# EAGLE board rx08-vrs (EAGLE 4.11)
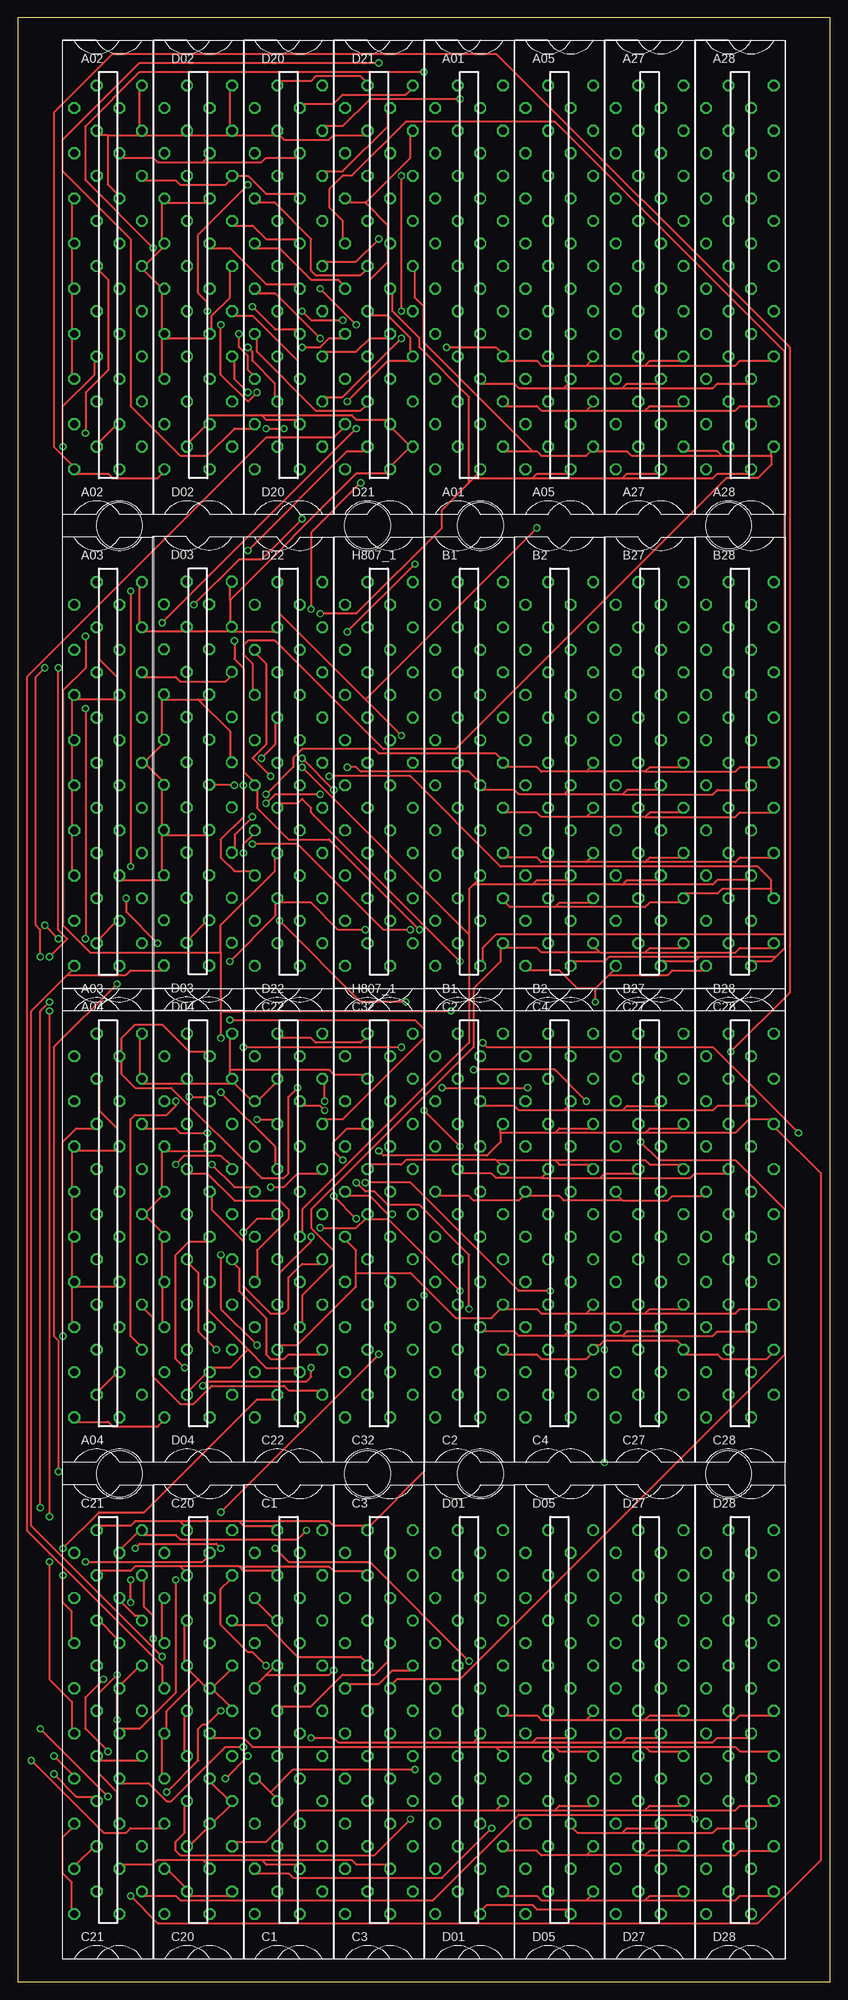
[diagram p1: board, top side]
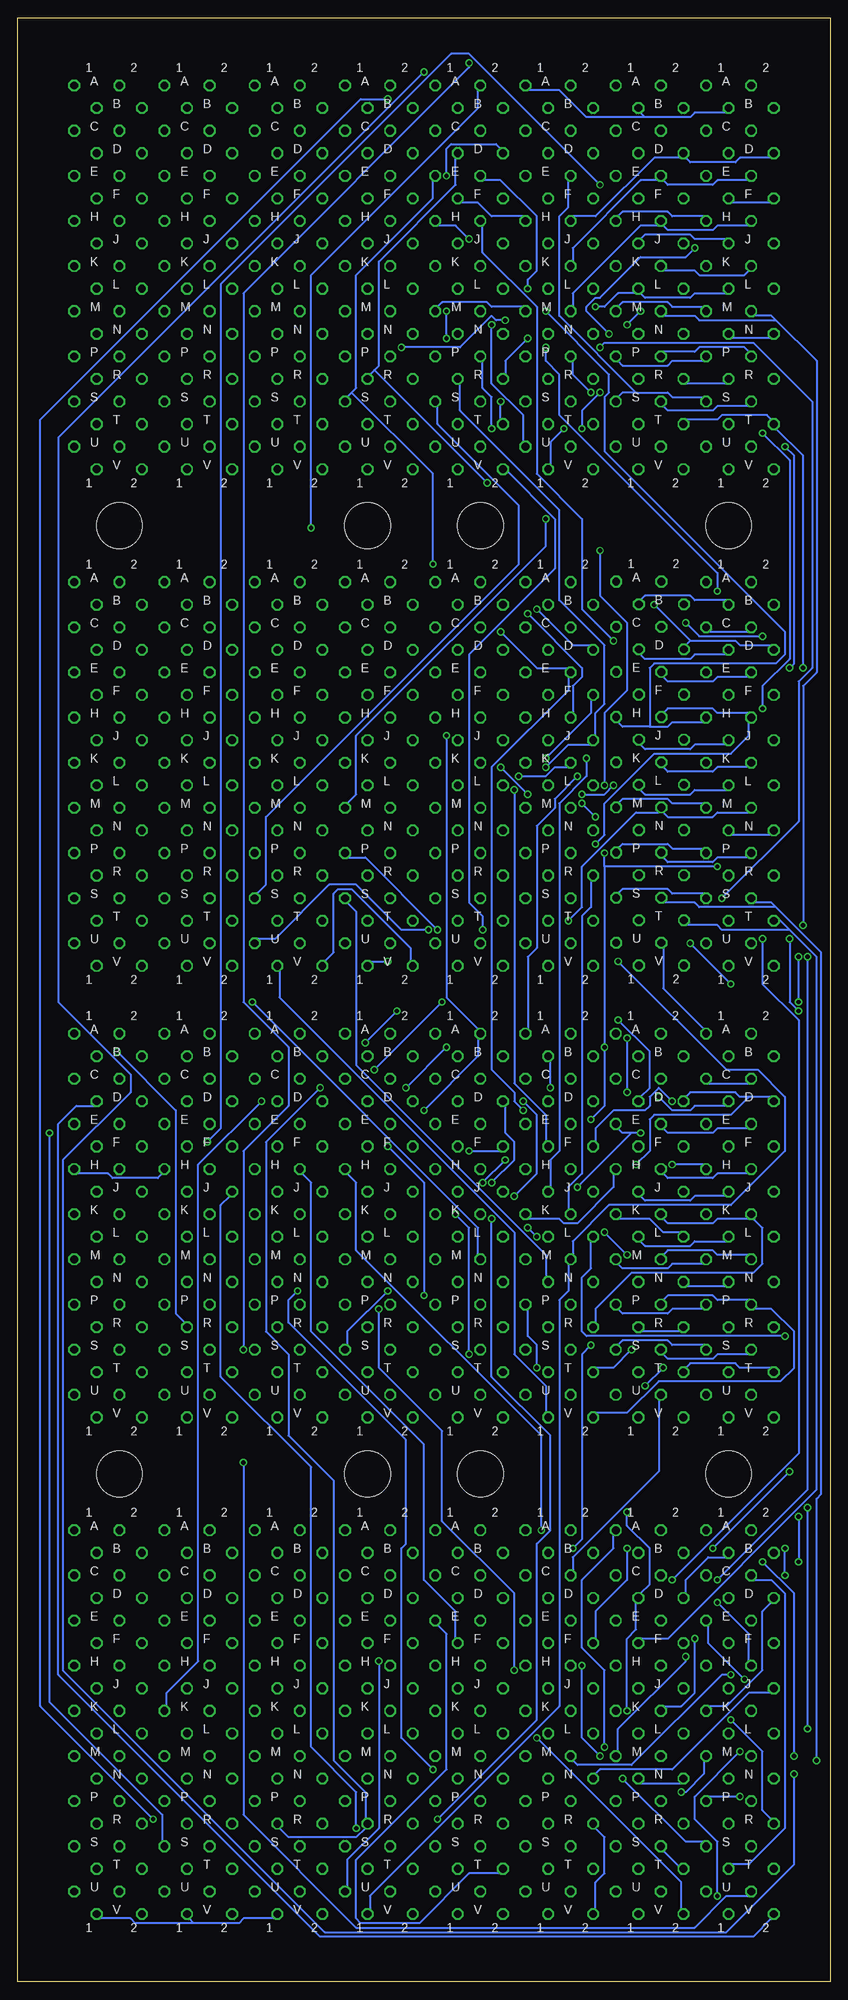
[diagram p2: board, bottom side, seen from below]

Size 114.3 x 276.23 mm. Coordinates in mm from the lower left corner, seen from the top.
Outline: 0,0 114.3,0 114.3,276.23 0,276.23 0,0
Copper layers (1*16): Top 0.035mm / dielectric 1.5mm / Bottom 0.035mm
Design rules "olimex10mil": minimum track width 10mil, minimum drill 24mil, track to track 10mil, track to pad 10mil, pad to pad 10mil, via to via 10mil, smd to smd 10mil, copper to edge 40mil, drill to drill 10mil, minimum pad ring 10mil, minimum via ring 8mil, stop-mask expansion 0mil, vias tented up to drill 0mil, thermal gap 10mil
Net classes: 1 Supply: width 1.905 mm, drill 0.508 mm

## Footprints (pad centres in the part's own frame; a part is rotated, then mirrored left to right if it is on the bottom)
H807 = drill 1.092 octagon: A1 4.763,28.575; A2 -1.587,28.575; B1 1.587,25.4; B2 -4.763,25.4; C1 4.763,22.225; C2 -1.587,22.225; D1 1.587,19.05; D2 -4.763,19.05; E1 4.763,15.875; E2 -1.587,15.875; F1 1.587,12.7; F2 -4.763,12.7; H1 4.763,9.525; H2 -1.587,9.525; J1 1.587,6.35; J2 -4.763,6.35; K1 4.763,3.175; K2 -1.587,3.175; L1 1.587,0; L2 -4.763,0; M1 4.763,-3.175; M2 -1.587,-3.175; N1 1.587,-6.35; N2 -4.763,-6.35; P1 4.763,-9.525; P2 -1.587,-9.525; R1 1.587,-12.7; R2 -4.763,-12.7; S1 4.763,-15.875; S2 -1.587,-15.875; T1 1.587,-19.05; T2 -4.763,-19.05; U1 4.763,-22.225; U2 -1.587,-22.225; V1 1.587,-25.4; V2 -4.763,-25.4
CBLOCK = hole 6.452: 7.938,68.263; 42.862,68.263

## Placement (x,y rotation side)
A01  [H807]  63.5,238.12 0 top
A02  M903  [H807]  12.7,238.12 0 top
A03  M903  [H807]  12.7,168.28 0 top
A04  M903  [H807]  12.7,104.78 0 top
A05  [H807]  76.2,238.12 0 top
A27  [H807]  88.9,238.12 0 top
A28  [H807]  101.6,238.12 0 top
B1  [H807]  63.5,168.28 0 top
B2  [H807]  76.2,168.28 0 top
B27  [H807]  88.9,168.28 0 top
B28  [H807]  101.6,168.28 0 top
C1  [H807]  38.1,34.92 0 top
C2  [H807]  63.5,104.78 0 top
C3  M310  [H807]  50.8,34.92 0 top
C4  [H807]  76.2,104.78 0 top
C20  [H807]  25.4,34.92 0 top
C21  [H807]  12.7,34.92 0 top
C22  M624  [H807]  38.1,104.78 0 top
C27  [H807]  88.9,104.78 0 top
C28  [H807]  101.6,104.78 0 top
C32  M002  [H807]  50.8,104.78 0 top
D01  [H807]  63.5,34.92 0 top
D02  M903  [H807]  25.4,238.12 0 top
D03  M903  [H807]  25.34,168.34 0 top
D04  M903  [H807]  25.4,104.78 0 top
D05  [H807]  76.2,34.92 0 top
D20  [H807]  38.1,238.12 0 top
D21  [H807]  50.8,238.12 0 top
D22  M002  [H807]  38.1,168.28 0 top
D27  [H807]  88.9,34.92 0 top
D28  [H807]  101.6,34.92 0 top
H807_1  H807  [H807]  50.8,168.28 0 top
U$1  [CBLOCK]  6.35,136.53 0 top
U$2  [CBLOCK]  57.15,136.53 0 top
U$3  [CBLOCK]  6.35,3.17 0 top
U$4  [CBLOCK]  57.15,3.17 0 top

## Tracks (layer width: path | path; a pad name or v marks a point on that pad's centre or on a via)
AC00L  (via drill 0.61)
  Top 0.254: D04.B1 26.67,130.81 24.13,130.81 20.32,134.62 16.51,134.62 14.61,132.72 14.61,130.81 A04.B1 14.61,129.54 14.61,127.64 16.51,125.73 21.59,125.73 34.29,113.03 37.47,113.03 38.1,113.67 38.1,124.46 v39.37,125.73
  Bottom 0.254: v39.37,125.73 39.37,129.54 C22.B1
AC01L  (via drill 0.61)
  Top 0.254: v24.13,124.46 26.67,124.46 D04.D1 | v29.84,135.25 55.88,135.25 57.15,133.99 57.15,132.72 45.72,121.28 43.18,121.28 C22.E1
  Bottom 0.254: v24.13,124.46 22.23,122.56 19.68,122.56 19.05,123.19 14.61,123.19 A04.D1 | v29.84,135.25 25.4,130.81 25.4,125.73 26.67,124.46 D04.D1
AC02L  (via drill 0.61)
  Top 0.254: v26.67,119.38 22.86,119.38 22.23,120.02 17.78,120.02 A04.E1 | v35.56,111.76 37.47,111.76 39.37,113.67 42.55,113.67 C22.H1
  Bottom 0.254: 27.94,119.38 29.21,119.38 29.84,120.02 D04.E1 | v26.67,119.38 27.94,119.38 | 27.94,119.38 v35.56,111.76
AC03L  (via drill 0.61)
  Top 0.254: v22.23,114.94 23.5,116.2 28.57,116.2 29.84,114.94 D04.H1
  Bottom 0.254: v22.23,114.94 17.78,114.94 A04.H1 | C22.K1 42.55,107.31 38.1,107.31 37.47,106.68 35.56,106.68 30.48,111.76 30.48,113.67 D04.H1
AC04L
  Top 0.254: C22.M1 42.55,100.97 40.01,100.97 38.1,99.06 38.1,94.61 37.47,93.98 35.56,93.98 31.75,97.79 31.75,104.14 27.3,108.58 27.3,110.49 D04.J1
  Bottom 0.254: A04.J1 14.61,110.49 19.05,110.49 19.68,109.86 26.04,109.86 26.67,110.49 D04.J1
AC05L  (via drill 0.61)
  Top 0.254: v41.27,86.36 41.27,85.09 40.64,84.45 26.67,84.45 v26.04,83.82 | v23.5,86.36 22.23,87.63 22.23,102.23 24.13,104.14 26.67,104.14 D04.L1
  Bottom 0.254: A04.L1 14.61,104.14 19.05,104.14 19.68,103.5 26.04,103.5 26.67,104.14 D04.L1 | v41.27,86.36 41.27,89.53 42.55,90.81 42.55,94.61 C22.P1 | v23.5,86.36 v26.04,83.82
AC06L
  Top 0.254: C22.S1 42.55,88.27 38.1,88.27 37.47,87.63 35.56,87.63 34.92,88.27 34.92,93.34 31.11,97.16 31.11,100.33 30.48,100.97 D04.M1
  Bottom 0.254: A04.M1 17.78,100.97 22.23,100.97 22.86,100.33 29.21,100.33 29.84,100.97 D04.M1
AC07L
  Top 0.254: C22.U1 42.55,83.19 38.1,83.19 37.47,83.82 27.3,83.82 24.77,81.28 22.86,81.28 19.05,85.09 19.05,93.34 17.78,94.61 A04.P1
  Bottom 0.254: A04.P1 17.78,94.61 22.23,94.61 22.86,93.98 29.21,93.98 29.84,94.61 D04.P1
AC08L  (via drill 0.61)
  Top 0.254: v22.23,123.83 22.23,123.19 20.95,121.92 16.51,121.92 15.88,121.28 15.88,90.81 17.14,89.53 A04.S1
  Bottom 0.254: A04.S1 17.78,89.53 22.23,89.53 22.86,90.17 29.21,90.17 29.84,89.53 D04.S1 | v22.23,123.83 24.13,125.73 25.4,124.46 25.4,123.19 26.04,122.56 30.48,122.56 33.02,120.02 33.02,118.11 C22.F2
AC09L  (via drill 0.61)
  Top 0.254: v27.3,114.94 30.48,111.76 33.02,111.76 C22.J2
  Bottom 0.254: 11.43,124.46 12.7,124.46 13.34,125.09 19.68,125.09 20.32,124.46 D04.D2 | 11.43,124.46 8.26,124.46 A04.D2 | v27.3,114.94 25.4,116.84 25.4,121.28 24.77,121.92 13.97,121.92 11.43,124.46
AC10L  (via drill 0.61)
  Top 0.254: v6.35,90.81 6.35,118.11 8.26,120.02 10.79,120.02 A04.E2
  Bottom 0.254: A04.E2 11.43,120.02 15.88,120.02 16.51,119.38 22.86,119.38 23.5,120.02 D04.E2 | v6.35,90.81 34.29,90.81 34.92,91.44 34.92,99.06 33.66,100.33 33.66,104.14 C22.L2
AC11L
  Top 0.254: C22.N2 33.66,99.06 33.66,102.87 38.1,107.31 38.1,108.58 36.83,109.86 30.48,109.86 26.67,113.67 24.13,113.67 D04.H2
  Bottom 0.254: A04.H2 11.43,113.67 15.88,113.67 16.51,113.03 22.86,113.03 23.5,113.67 D04.H2
BAC00
  Bottom 0.254: 26.04,262.25 19.68,262.25 19.05,262.89 14.61,262.89 A02.B1 | 26.04,262.25 26.67,262.89 D02.B1 | 26.04,262.25 34.29,262.25 38.1,266.06 42.55,266.06 D20.A1
BAC01
  Top 0.254: 26.04,255.91 19.68,255.91 19.05,256.54 14.61,256.54 A02.D1 | 26.04,255.91 26.67,256.54 D02.D1 | 26.04,255.91 34.29,255.91 34.92,256.54 39.37,256.54 D20.D1
BAC02
  Top 0.254: A02.E1 17.78,253.37 22.23,253.37 22.86,252.73 29.21,252.73 29.84,253.37 D02.E1 32.38,254 34.92,251.46 39.37,251.46 D20.F1
BAC03
  Top 0.254: D20.J1 39.37,245.11 34.92,245.11 33.02,247.01 30.48,247.01 D02.H1
  Bottom 0.254: A02.H1 17.78,248.28 22.23,248.28 22.86,248.92 29.21,248.92 29.84,248.28 D02.H1
BAC04
  Top 0.254: D20.L1 39.37,238.76 34.92,238.76 29.84,243.84 27.3,243.84 D02.J1
  Bottom 0.254: A02.J1 14.61,245.11 19.05,245.11 19.68,245.75 26.04,245.75 26.67,245.11 D02.J1
BAC05  (via drill 0.61)
  Top 0.254: v33.02,235.59 36.2,232.41 39.37,232.41 D20.N1
  Bottom 0.254: A02.L1 14.61,237.49 19.05,237.49 19.68,236.85 26.04,236.85 26.67,237.49 D02.L1 27.3,237.49 29.84,237.49 31.75,235.59 v33.02,235.59
BAC06
  Top 0.254: D20.R1 39.37,226.06 39.37,227.97 33.02,234.31 30.48,234.31 D02.M1
  Bottom 0.254: A02.M1 17.78,235.59 22.23,235.59 22.86,236.22 29.21,236.22 29.84,235.59 D02.M1
BAC07  (via drill 0.61)
  Top 0.254: v34.92,218.44 v37.47,218.44 | v32.38,223.52 30.48,225.43 30.48,227.97 D02.P1
  Bottom 0.254: A02.P1 17.78,227.97 22.23,227.97 22.86,227.33 29.21,227.33 29.84,227.97 D02.P1 | v37.47,218.44 39.37,216.53 39.37,213.36 D20.V1 | v34.92,218.44 34.92,220.98 v32.38,223.52
BAC08
  Bottom 0.254: 27.3,223.52 29.21,223.52 29.84,222.88 D02.S1 | 27.3,223.52 22.86,223.52 22.23,222.88 17.78,222.88 A02.S1 | 27.3,223.52 38.1,234.31 38.1,248.28 36.83,249.56 36.83,253.37 D20.E2
BAC09
  Bottom 0.254: A02.D2 8.26,256.54 12.7,256.54 13.34,255.91 19.68,255.91 20.32,256.54 D02.D2 20.95,256.54 24.77,256.54 33.02,248.28 36.2,248.28 D20.H2
BAC10
  Bottom 0.254: A02.E2 11.43,253.37 15.88,253.37 16.51,252.73 22.86,252.73 23.5,253.37 D02.E2 24.13,253.37 26.67,253.37 36.2,243.84 36.2,241.94 D20.K2
BAC11
  Bottom 0.254: A02.H2 11.43,247.01 15.88,247.01 16.51,246.38 22.86,246.38 23.5,247.01 D02.H2 24.13,247.01 26.67,247.01 36.2,237.49 36.2,235.59 D20.M2
BACLR
  Bottom 0.254: D04.P2 23.5,95.89 22.86,96.52 16.51,96.52 15.88,95.89 11.43,95.89 A04.P2 10.79,94.61 8.26,94.61 5.08,91.44 5.08,86.36 6.99,84.45 24.13,84.45 28.57,80.01 33.02,80.01 C22.V2
BINIT  (via drill 0.61)
  Top 0.254: D02.V2 20.32,212.09 19.68,211.46 13.34,211.46 12.7,212.09 8.26,212.09 A02.V2 7.62,213.36 5.08,215.9 5.08,262.89 13.34,271.14 67.31,271.14 108.58,229.87 108.58,139.06 v100.33,130.81 | 76.83,90.81 70.48,90.81 69.85,91.44 65.41,91.44 C2.R1 | 76.83,90.81 77.47,91.44 C4.R1 | 85.09,90.81 85.72,91.44 90.17,91.44 C27.R1 | 85.09,90.81 76.83,90.81 | 85.09,90.81 97.79,90.81 98.42,91.44 102.87,91.44 C28.R1
  Bottom 0.254: v100.33,130.81 92.08,122.56 92.08,93.98 90.81,92.71 C27.R1
BIOP1  (via drill 0.61)
  Top 0.254: v22.23,56.52 22.23,40.64 17.14,35.56 14.61,35.56 C21.L1 | v9.53,179.07 v9.53,146.69 | v9.53,217.81 9.53,223.52 12.7,226.69 12.7,239.4 11.43,240.66 A02.K2
  Bottom 0.254: v22.23,56.52 4.45,74.3 4.45,135.25 9.53,140.34 v9.53,146.69 | v9.53,179.07 9.53,182.25 5.71,186.06 5.71,214 v9.53,217.81 | D02.K2 23.5,240.66 19.05,240.66 18.41,240.03 12.06,240.03 11.43,240.66 A02.K2
BIOP2  (via drill 0.61)
  Top 0.254: v4.45,59.05 4.45,42.55 7.62,39.37 7.62,35.56 C21.L2 | v4.45,136.53 v4.45,65.41 | v3.81,148.59 v5.71,146.69
  Bottom 0.254: v4.45,65.41 v4.45,59.05 | v4.45,136.53 5.71,137.79 v5.71,146.69 | v3.81,148.59 3.81,182.25 1.91,184.15 1.91,227.97 7.62,233.68 | 7.62,233.68 8.26,234.31 10.79,234.31 A02.M2 | 7.62,233.68 18.41,233.68 19.05,234.31 23.5,234.31 D02.M2
BIOP4  (via drill 0.61)
  Top 0.254: v3.17,35.56 v12.7,26.04 | v3.17,66.67 3.17,136.53 v4.45,137.79 | v4.45,144.15 6.99,146.69 5.71,147.96 v5.71,184.78 | v6.35,215.9 6.35,221.62 10.79,226.06 10.79,227.97 A02.P2
  Bottom 0.254: v12.7,26.04 17.14,26.04 C21.P1 | v3.17,35.56 v3.17,66.67 | v4.45,137.79 v4.45,144.15 | v5.71,184.78 5.08,185.42 5.08,214.63 v6.35,215.9 | D02.P2 23.5,229.24 19.05,229.24 18.41,229.87 12.06,229.87 11.43,229.24 A02.P2
BIRQ  (via drill 0.61)
  Top 0.254: v27.94,88.9 25.4,91.44 25.4,99.69 24.13,100.97 D04.M2
  Bottom 0.254: A04.M2 11.43,102.23 15.88,102.23 16.51,102.87 22.86,102.87 23.5,102.23 D04.M2 | v27.94,88.9 30.48,86.36 33.02,86.36 C22.T2
BMB00
  Bottom 0.254: A03.B1 14.61,194.31 19.05,194.31 19.68,194.94 26.04,194.94 26.67,194.31 D03.B1
BMB01
  Bottom 0.254: A03.D1 14.61,186.69 19.05,186.69 19.68,186.06 26.04,186.06 26.67,186.69 D03.D1
BMB02
  Top 0.254: A03.E1 17.78,183.51 22.23,183.51 22.86,182.88 29.21,182.88 29.84,183.51 D03.E1
BMB03
  Bottom 0.254: A03.J1 14.61,173.99 19.05,173.99 19.68,173.35 26.04,173.35 26.67,173.99 D03.J1
BMB03L  (via drill 0.61)
  Top 0.254: 80.01,227.33 73.66,227.33 73.03,227.97 68.58,227.97 A01.P1 67.94,229.24 67.31,229.87 v60.33,229.87 | 80.01,227.33 80.64,227.97 A05.P1 | 88.27,227.33 88.9,227.97 93.34,227.97 A27.P1 | 80.01,227.33 88.27,227.33 | 88.27,227.33 100.97,227.33 101.6,227.97 106.05,227.97 A28.P1 | v40.01,234.95 41.27,233.68 v45.72,233.68
  Bottom 0.254: 25.4,176.53 29.21,176.53 29.84,177.16 D03.H1 | 25.4,176.53 22.86,176.53 22.23,177.16 17.78,177.16 A03.H1 | 25.4,176.53 25.4,184.78 24.77,185.42 7.62,185.42 6.35,186.69 6.35,189.87 31.75,215.26 31.75,222.88 31.11,223.52 31.11,226.06 v40.01,234.95 | v45.72,233.68 46.99,233.68 47.62,234.31 52.07,229.87 v60.33,229.87
BMB04
  Bottom 0.254: A03.M1 17.78,165.74 22.23,165.74 22.86,166.37 29.21,166.37 29.84,165.74 D03.M1
BMB04L  (via drill 0.61)
  Top 0.254: 80.01,170.18 73.66,170.18 73.03,170.81 68.58,170.81 B1.K1 67.94,172.09 67.31,172.72 50.8,172.72 50.16,173.35 40.01,173.35 38.73,172.09 38.73,170.81 v34.92,167 | 80.01,170.18 80.64,170.81 B2.K1 | 88.27,170.18 88.9,170.81 93.34,170.81 B27.K1 | 88.27,170.18 80.01,170.18 | 88.27,170.18 100.97,170.18 101.6,170.81 106.05,170.81 B28.K1 | v30.48,168.28 27.3,168.28 D03.L1
  Bottom 0.254: A03.L1 14.61,167.64 19.05,167.64 19.68,167 26.04,167 26.67,167.64 D03.L1 | v30.48,168.28 31.75,167 v34.92,167
BMB05
  Bottom 0.254: A03.S1 17.78,153.03 22.23,153.03 22.86,153.67 29.21,153.67 29.84,153.03 D03.S1
BMB05L  (via drill 0.61)
  Top 0.254: 76.83,167 70.48,167 69.85,167.64 65.41,167.64 B1.L1 64.77,168.91 63.5,170.18 48.26,170.18 47.62,170.81 v46.35,170.81 | 76.83,167 77.47,167.64 B2.L1 | 85.09,167 85.72,167.64 90.17,167.64 B27.L1 | 85.09,167 76.83,167 | 85.09,167 97.79,167 98.42,167.64 102.87,167.64 B28.L1 | v33.02,163.83 30.48,161.29 30.48,159.38 D03.P1 | v34.92,165.74 36.2,167 v42.55,167
  Bottom 0.254: A03.P1 17.78,159.38 22.23,159.38 22.86,160.02 29.21,160.02 29.84,159.38 D03.P1 | v34.92,165.74 v33.02,163.83 | v46.35,170.81 v42.55,167
BMB06
  Bottom 0.254: A03.E2 11.43,183.51 15.88,183.51 16.51,182.88 22.86,182.88 23.5,183.51 D03.E2
BMB06L  (via drill 0.61)
  Top 0.254: 80.01,163.83 73.66,163.83 73.03,164.47 68.58,164.47 B1.M1 | 80.01,163.83 80.64,164.47 B2.M1 | 88.27,163.83 88.9,164.47 93.34,164.47 B27.M1 | 88.27,163.83 80.01,163.83 | 88.27,163.83 100.97,163.83 101.6,164.47 106.05,164.47 B28.M1 | v24.77,193.68 31.11,200.03 34.29,200.03 v40.01,205.74
  Bottom 0.254: 19.68,188.59 13.34,188.59 12.7,187.96 8.26,187.96 A03.D2 | 19.68,188.59 20.32,187.96 D03.D2 | v24.77,193.68 19.68,188.59 | v40.01,205.74 40.01,201.93 66.67,175.26 66.67,167 67.94,165.74 B1.M1
BMB07
  Bottom 0.254: A03.K2 11.43,170.81 15.88,170.81 16.51,170.18 22.86,170.18 23.5,170.81 D03.K2
BMB07L  (via drill 0.61)
  Top 0.254: 80.01,157.48 73.66,157.48 73.03,158.12 68.58,158.12 B1.P1 | 80.01,157.48 80.64,158.12 B2.P1 | 88.27,157.48 88.9,158.12 93.34,158.12 B27.P1 | 88.27,157.48 80.01,157.48 | 88.27,157.48 100.97,157.48 101.6,158.12 106.05,158.12 B28.P1 | v33.02,160.02 39.37,160.02 51.44,147.96 v55.24,147.96
  Bottom 0.254: D03.H2 23.5,178.44 22.86,179.07 16.51,179.07 15.88,178.44 11.43,178.44 A03.H2 11.43,177.16 11.43,175.26 13.97,172.72 24.77,172.72 31.75,165.74 31.75,161.29 v33.02,160.02 | v55.24,147.96 65.41,158.12 67.94,158.12 B1.P1
BMB08
  Bottom 0.254: A03.P2 11.43,158.12 15.88,158.12 16.51,157.48 22.86,157.48 23.5,158.12 D03.P2
BMB08L  (via drill 0.61)
  Top 0.254: 80.01,36.83 73.66,36.83 73.03,37.47 68.58,37.47 D01.K1 | 80.01,36.83 80.64,37.47 D05.K1 | 88.27,36.83 88.9,37.47 93.34,37.47 D27.K1 | 80.01,36.83 88.27,36.83 | 88.27,36.83 100.97,36.83 101.6,37.47 106.05,37.47 D28.K1 | v36.83,149.22 48.26,137.79 v54.61,137.79 | v64.14,128.27 75.56,128.27 v80.01,123.83
  Bottom 0.254: A03.M2 11.43,164.47 15.88,164.47 16.51,163.83 22.86,163.83 23.5,164.47 D03.M2 24.13,164.47 27.3,164.47 34.92,156.84 34.92,151.13 v36.83,149.22 | v64.14,128.27 v54.61,137.79 | v80.01,123.83 88.9,114.94 88.9,45.09 93.34,40.64 93.34,38.73 D27.K1
BMB09  (via drill 0.61)
  Top 0.254: v1.91,31.11 12.06,20.95 15.24,20.95 15.88,21.59 20.32,21.59 C20.R2
  Bottom 0.254: v1.91,31.11 1.91,67.94 1.27,68.58 1.27,144.78 7.62,151.13 | 7.62,151.13 8.26,151.76 10.79,151.76 A03.S2 | 7.62,151.13 18.41,151.13 19.05,151.76 23.5,151.76 D03.S2
BMB10
  Bottom 0.254: 5.71,147.96 7.62,149.86 A03.T2 | 5.71,147.96 1.91,144.15 1.91,69.22 22.86,48.26 26.67,48.26 C20.F1 | 5.71,147.96 15.24,147.96 15.88,148.59 20.32,148.59 D03.T2
BMB11  (via drill 0.61)
  Top 0.254: v20.32,45.72 1.91,64.14 1.91,136.53 6.99,141.6 | 6.99,141.6 7.62,142.24 A03.V2 | 6.99,141.6 15.24,141.6 15.88,142.24 20.32,142.24 D03.V2
  Bottom 0.254: v20.32,45.72 20.32,45.09 29.84,35.56 29.84,32.38 C20.M1
BRD_L  (via drill 0.61)
  Top 0.254: v55.24,22.86 50.16,17.78 22.86,17.78 22.23,18.41 22.23,19.68 23.5,20.95 23.5,24.77 C20.P2 | v47.62,107.31 v44.45,110.49 | v43.18,123.83 43.18,126.36 C22.C1
  Bottom 0.254: v55.24,22.86 41.27,36.83 41.27,61.59 39.37,63.5 39.37,76.83 47.62,85.09 v47.62,107.31 | v44.45,110.49 41.27,113.67 41.27,121.92 v43.18,123.83
BRUN
  Bottom 0.254: A04.S2 11.43,88.27 15.88,88.27 16.51,87.63 22.86,87.63 23.5,88.27 D04.S2
BSKIP
  Bottom 0.254: D04.K2 23.5,107.31 22.86,106.68 16.51,106.68 15.88,107.31 11.43,107.31 A04.K2 10.79,107.31 9.53,106.05 9.53,100.97 10.79,99.69 27.94,99.69 33.02,94.61 33.02,92.71 C22.R2
BTS1  (via drill 0.61)
  Top 0.254: v15.88,53.34 v15.88,56.52 | v3.17,144.15 3.17,147.96 2.54,148.59 2.54,183.51 v3.81,184.78
  Bottom 0.254: v15.88,53.34 11.43,48.9 11.43,45.09 C21.H2 | v15.88,56.52 3.17,69.22 v3.17,144.15 | v3.81,184.78 3.81,214.63 7.62,218.44 A02.T2 8.26,219.71 8.89,220.34 15.24,220.34 15.88,219.71 20.32,219.71 D02.T2
BTS3
  Bottom 0.254: A02.S2 11.43,221.62 15.88,221.62 16.51,220.98 22.86,220.98 23.5,221.62 D02.S2
BWR_L  (via drill 0.61)
  Top 0.254: 48.9,250.19 46.35,250.19 D21.F2 | 48.9,250.19 52.07,247.01 52.07,245.11 D21.J1 52.07,243.84 52.07,241.94 49.53,239.4 49.53,235.59 D21.M2 49.53,234.31 52.07,234.31 55.24,231.14 55.24,229.24 D21.P1 55.24,227.97 52.07,227.97 v46.35,222.25 | 48.9,250.19 55.24,256.54 55.24,259.71 D21.C1 | C20.J2 20.32,41.91 20.32,44.45 1.27,63.5 1.27,183.51 34.92,217.17 44.45,217.17 45.72,218.44 D21.T2
  Bottom 0.254: v46.35,222.25 46.35,219.71 D21.T2
C0L  (via drill 0.61)
  Top 0.254: C21.E1 17.14,51.44 16.51,51.44 14.61,53.34 C21.D1 | v50.8,116.84 51.44,116.2 66.04,116.2 67.94,118.11 67.94,119.38 | 67.94,119.38 67.94,120.02 C2.E1 | 75.56,119.38 76.2,120.02 80.64,120.02 C4.E1 | 75.56,119.38 67.94,119.38 | 88.27,119.38 88.9,120.02 93.34,120.02 C27.E1 | 88.27,119.38 75.56,119.38 | 88.27,119.38 100.97,119.38 102.87,121.28 106.05,121.28 C28.E1 106.68,120.02 113.03,113.67 113.03,17.14 104.14,8.26 19.68,8.26 v15.88,12.06 | v12.06,42.55 9.53,40.01 9.53,35.56 v12.7,32.38
  Bottom 0.254: v50.8,116.84 46.35,116.84 C32.F2 | v12.06,42.55 17.14,47.62 17.14,50.16 C21.E1 | v12.7,32.38 19.05,26.04 19.05,22.86 15.88,19.68 v15.88,12.06
C1L  (via drill 0.61)
  Top 0.254: C20.F2 20.32,48.26 20.32,53.34 C20.D2 | C21.B1 14.61,60.96 17.14,63.5 C21.A1 17.78,62.87 22.23,62.87 22.86,62.23 39.37,62.23 v40.64,63.5 | 67.31,115.57 54.61,115.57 53.98,114.94 49.53,114.94 C32.H2 | 67.31,115.57 67.94,114.94 C2.H1 | 75.56,115.57 76.2,114.94 80.64,114.94 C4.H1 | 67.31,115.57 75.56,115.57 | 75.56,115.57 88.27,115.57 88.9,114.94 93.34,114.94 C27.H1
  Bottom 0.254: C20.D2 20.32,54.61 20.32,56.52 17.14,59.69 14.61,59.69 C21.B1 | C28.H1 106.05,113.67 101.6,113.67 100.97,113.03 94.61,113.03 93.98,113.67 C27.H1 | v40.64,63.5 40.64,76.83 66.67,102.87 66.67,112.39 67.94,113.67 C2.H1
C20U1
  Top 0.254: 27.3,41.27 29.84,38.73 C20.K1 | 25.4,42.55 26.67,41.27 C20.J1 27.3,41.27 | 25.4,42.55 24.13,43.81 C20.H2 23.5,45.09 23.5,50.16 C20.E2 | 27.3,41.27 29.84,43.81 C20.H1 | C20.N2 20.32,29.21 20.32,34.29 C20.L2 20.95,35.56 20.95,38.1 25.4,42.55 | C20.T2 20.95,15.88 23.5,13.34 C20.U2 24.13,12.06 29.84,12.06 C20.U1 | C20.S2 24.13,19.05 26.67,21.59 C20.R1 27.3,22.23 29.84,24.77 C20.P1 29.84,25.4 27.3,27.94 C20.N1
  Bottom 0.254: C20.S2 23.5,18.41 20.95,15.88 C20.T2 | C20.N2 20.95,27.94 26.67,27.94 C20.N1
C21U1  (via drill 0.61)
  Top 0.254: v95.25,22.86 94.61,23.5 70.48,23.5 58.42,11.43 22.86,11.43 22.23,12.06 17.78,12.06 C21.U1 | v62.23,264.8 49.53,264.8 45.72,260.99 43.18,260.99 D20.C1
  Bottom 0.254: v95.25,22.86 111.12,38.73 111.12,219.71 66.04,264.8 v62.23,264.8
DATA00LL  (via drill 0.61)
  Top 0.254: v35.56,169.54 33.02,172.09 34.92,173.99 34.92,185.42 33.66,186.69 D22.D2 | 76.83,224.16 70.48,224.16 69.85,224.79 65.41,224.79 A01.R1 | 76.83,224.16 77.47,224.79 A05.R1 | 85.09,224.16 85.72,224.79 90.17,224.79 A27.R1 | 76.83,224.16 85.09,224.16 | 85.09,224.16 97.79,224.16 98.42,224.79 102.87,224.79 A28.R1 | v41.27,193.04 41.27,203.84 v48.26,210.82
  Bottom 0.254: v35.56,169.54 38.73,166.37 38.73,165.1 41.27,162.56 41.27,145.41 42.55,144.15 42.55,133.99 C22.A1 | 64.14,226.69 64.77,226.06 A01.R1 | 64.14,226.69 63.5,227.33 63.5,241.94 52.7,252.73 52.7,256.54 D21.D1 | v41.27,193.04 36.2,187.96 33.66,187.96 D22.D2 | v48.26,210.82 64.14,226.69
DATA01L  (via drill 0.61)
  Top 0.254: v43.18,122.56 42.55,123.19 40.01,123.19 C22.D1 | 80.01,220.98 73.66,220.98 73.03,221.62 68.58,221.62 A01.S1 | 80.01,220.98 80.64,221.62 A05.S1 | 88.27,220.98 88.9,221.62 93.34,221.62 A27.S1 | 80.01,220.98 88.27,220.98 | 88.27,220.98 100.97,220.98 101.6,221.62 106.05,221.62 A28.S1 | v55.88,199.39 v46.35,189.87
  Bottom 0.254: v43.18,122.56 44.45,123.83 44.45,125.09 47.62,128.27 47.62,170.81 36.83,181.61 36.83,183.51 D22.E2 36.83,184.78 41.27,184.78 v46.35,189.87 | 67.31,223.52 67.94,222.88 A01.S1 | 67.31,223.52 66.67,224.16 66.67,240.03 55.88,250.82 55.88,253.37 D21.E1 | v55.88,199.39 55.88,212.09 67.31,223.52
DATA02L  (via drill 0.61)
  Top 0.254: 72.39,215.26 73.03,215.26 73.66,214.63 80.01,214.63 80.64,215.26 A05.U1 81.28,215.26 85.72,215.26 86.36,214.63 99.06,214.63 | 72.39,215.26 68.58,215.26 A01.U1 | 72.39,215.26 57.15,230.5 57.15,235.59 55.88,236.85 55.88,240.66 D21.K1 | 106.05,214.63 106.05,215.26 A28.U1 | 106.05,214.63 106.05,213.36 104.14,211.46 99.69,211.46 61.59,173.35 51.44,173.35 36.2,188.59 32.38,188.59 31.75,187.96 31.75,186.69 33.02,185.42 33.02,181.61 D22.F2 | v40.01,172.09 v44.45,167.64 | 99.06,214.63 98.42,215.26 93.98,215.26 A27.U1 | 99.06,214.63 106.05,214.63
  Bottom 0.254: v44.45,167.64 44.45,126.36 40.01,121.92 40.01,118.11 C22.F1 | v40.01,172.09 33.66,178.44 33.66,180.34 D22.F2
DATA03L  (via drill 0.61)
  Top 0.254: v42.55,192.41 47.62,192.41 59.69,204.47 59.69,207.01 63.5,210.82 | 64.14,211.46 64.77,212.09 A01.V1 | 63.5,210.82 64.14,211.46 | v34.29,172.09 36.2,173.99 36.2,177.16 D22.H2 | 63.5,210.82 63.5,222.88 56.52,229.87 56.52,231.14 52.7,234.95 52.7,237.49 D21.L1 | 72.39,211.46 73.03,212.09 77.47,212.09 A05.V1 | 64.14,211.46 72.39,211.46 | 85.09,211.46 85.72,212.09 90.17,212.09 A27.V1 | 72.39,211.46 85.09,211.46 | 85.09,211.46 97.79,211.46 98.42,212.09 102.87,212.09 A28.V1
  Bottom 0.254: v42.55,192.41 34.92,184.78 34.92,183.51 36.2,182.25 36.2,178.44 D22.H2 | v34.29,172.09 34.29,169.54 38.1,165.74 38.1,116.84 39.37,115.57 39.37,111.76 C22.J1
DATA04L  (via drill 0.61)
  Top 0.254: 63.5,147.32 63.5,153.67 64.14,154.31 | 63.5,147.32 63.5,132.08 40.01,108.58 40.01,105.41 C22.L1 | 64.14,154.31 64.77,154.94 B1.R1 | 72.39,154.31 73.03,154.94 77.47,154.94 B2.R1 | 72.39,154.31 64.14,154.31 | 85.09,154.31 85.72,154.94 90.17,154.94 B27.R1 | 85.09,154.31 72.39,154.31 | 85.09,154.31 97.79,154.31 98.42,154.94 102.87,154.94 B28.R1 | 63.5,147.32 v40.01,170.81
  Bottom 0.254: v40.01,170.81 36.83,173.99 33.66,173.99 D22.J2 33.02,175.26 33.02,178.44 31.75,179.71 31.75,187.96 38.1,194.31 38.1,207.01 52.07,220.98 52.07,224.79 D21.R1
DATA05L  (via drill 0.61)
  Top 0.254: v43.81,169.54 55.24,169.54 67.94,156.84 104.14,156.84 106.05,154.94 106.05,153.67 | 106.05,153.67 106.05,153.03 B28.S1 | 106.05,153.67 99.06,153.67 98.42,153.03 93.98,153.03 B27.S1 93.34,151.76 88.9,151.76 88.27,151.13 75.56,151.13 | 75.56,151.13 76.2,151.76 80.64,151.76 B2.S1 | 75.56,151.13 69.22,151.13 68.58,151.76 B1.S1
  Bottom 0.254: v43.81,169.54 40.01,169.54 38.73,170.81 36.83,170.81 D22.K2 | C22.N1 40.01,99.06 40.01,102.23 66.67,128.91 66.67,150.5 67.94,151.76 B1.S1 | D21.S1 55.24,221.62 55.24,219.07 43.81,207.65 43.81,199.39 79.38,163.83 79.38,154.31 80.64,153.03 B2.S1
DATA06L  (via drill 0.61)
  Top 0.254: C22.R1 40.01,92.71 40.01,96.52 44.45,100.97 44.45,102.87 41.27,106.05 41.27,108.58 64.14,131.44 64.14,139.7 67.94,143.51 67.94,145.41 B1.U1 68.58,145.41 73.03,145.41 73.66,144.78 81.92,144.78 | v56.52,147.96 43.81,160.66 38.1,160.66 33.66,165.1 33.66,167.64 D22.L2 33.02,168.91 31.75,170.18 31.75,184.78 30.48,186.06 v30.48,188.59 | 88.27,144.78 88.9,145.41 93.34,145.41 B27.U1 | 81.92,144.78 88.27,144.78 | 81.92,144.78 81.28,145.41 B2.U1 | 88.27,144.78 100.97,144.78 101.6,145.41 106.05,145.41 B28.U1
  Bottom 0.254: v56.52,147.96 60.33,147.96 66.67,154.31 70.48,154.31 78.11,146.69 80.64,146.69 B2.U1 | v30.48,188.59 34.92,193.04 34.92,205.74 41.27,212.09 41.27,235.59 48.9,243.21 48.9,247.01 D21.H2
DATA07L  (via drill 0.61)
  Top 0.254: v62.23,143.51 41.27,164.47 41.27,165.1 40.01,166.37 39.37,165.74 36.83,165.74 D22.M2 | 107.95,147.32 107.95,145.41 106.68,144.15 | 107.95,147.32 107.95,229.24 75.56,261.62 54.61,261.62 46.99,254 45.72,254 43.81,252.09 43.81,249.56 45.72,247.65 45.72,245.11 D21.J2 | 106.68,144.15 106.05,143.51 103.5,143.51 B28.V1 | 95.89,144.15 95.25,143.51 90.81,143.51 B27.V1 | 106.68,144.15 95.89,144.15 | 107.95,147.32 67.31,147.32 65.41,145.41 65.41,143.51 B1.V1 | 95.89,144.15 83.19,144.15 82.55,143.51 78.11,143.51 B2.V1
  Bottom 0.254: C22.V1 40.01,80.01 40.01,83.82 44.45,88.27 44.45,105.41 77.47,138.43 77.47,142.24 B2.V1 | v62.23,143.51 64.77,143.51 B1.V1
DATA08L  (via drill 0.61)
  Top 0.254: 85.09,20.95 85.72,21.59 90.17,21.59 D27.R1 | 85.09,20.95 78.74,20.95 78.11,21.59 D05.R1 | 85.09,20.95 97.79,20.95 98.42,21.59 102.87,21.59 D28.R1 | v33.66,121.28 36.2,121.28 C22.E2 | v31.75,158.75 31.75,160.02 33.02,161.29 D22.N2 | v40.01,229.87 42.55,229.87 43.81,231.14 45.72,231.14 D21.N2 | v15.88,195.58 v15.88,156.84 | v59.69,125.73 v71.75,125.73 | v31.75,131.44 v53.98,131.44
  Bottom 0.254: D05.R1 77.47,21.59 76.2,20.32 66.67,20.32 65.41,21.59 D01.R1 65.41,22.86 65.41,26.67 69.85,31.11 69.85,70.48 76.2,76.83 76.2,88.27 79.38,91.44 79.38,118.11 v71.75,125.73 | v33.66,121.28 31.75,123.19 v31.75,131.44 31.75,156.84 | 31.75,156.84 v31.75,158.75 | v40.01,229.87 40.01,227.97 38.1,226.06 38.1,220.34 15.88,198.12 v15.88,195.58 | v15.88,156.84 31.75,156.84 | v53.98,131.44 v59.69,125.73
DATA09L  (via drill 0.61)
  Top 0.254: 80.01,17.78 73.66,17.78 73.03,18.41 68.58,18.41 D01.S1 | 80.01,17.78 80.64,18.41 D05.S1 | 88.27,17.78 88.9,18.41 93.34,18.41 D27.S1 | 88.27,17.78 80.01,17.78 | 88.27,17.78 100.97,17.78 101.6,18.41 106.05,18.41 D28.S1 | v28.57,125.09 36.2,117.47 36.2,114.94 C22.H2 | 28.57,144.78 28.57,148.59 36.2,156.21 36.2,158.12 D22.P2 | 28.57,144.78 28.57,136.53 | 28.57,136.53 v28.57,132.72 | v47.62,218.44 v20.32,191.13 | v9.53,189.23 9.53,184.78 6.35,181.61 6.35,148.59 10.16,144.78 28.57,144.78 | v109.86,119.38 97.79,131.44 66.04,131.44 v65.41,132.08 | 28.57,136.53 v60.96,136.53
  Bottom 0.254: v28.57,132.72 v28.57,125.09 | v47.62,218.44 47.62,222.88 48.9,224.16 48.9,227.97 D21.P2 | v20.32,191.13 18.41,189.23 v9.53,189.23 | v109.86,119.38 109.86,39.37 93.98,23.5 93.98,19.68 D27.S1 | v60.96,136.53 v65.41,132.08
DATA10L  (via drill 0.61)
  Top 0.254: 80.01,11.43 73.66,11.43 73.03,12.06 68.58,12.06 D01.U1 | 80.01,11.43 80.64,12.06 D05.U1 | 88.27,11.43 88.9,12.06 93.34,12.06 D27.U1 | 80.01,11.43 88.27,11.43 | 88.27,11.43 100.97,11.43 101.6,12.06 106.05,12.06 D28.U1 | v32.38,201.29 46.35,215.26 48.9,215.26 D21.U2 | v31.75,168.28 31.75,163.83 28.57,160.66 28.57,158.12 30.48,156.21 33.02,156.21 D22.R2 | v63.5,45.09 49.53,59.05 38.1,59.05 v36.2,60.96 | v33.66,89.53 28.57,94.61 v28.57,102.23 | v31.75,105.41 33.66,107.31 36.2,107.31 C22.K2
  Bottom 0.254: D22.R2 33.66,154.94 33.66,151.13 34.92,149.86 34.92,113.67 36.83,111.76 36.83,108.58 C22.K2 | v32.38,201.29 32.38,194.94 28.57,191.13 28.57,181.61 31.75,178.44 v31.75,168.28 | v63.5,45.09 63.5,21.59 67.94,17.14 67.94,13.34 D01.U1 | v36.2,60.96 34.92,62.23 34.92,88.27 v33.66,89.53 | v31.75,105.41 v28.57,102.23
DATA11L  (via drill 0.61)
  Top 0.254: v48.9,147.96 45.09,147.96 41.27,151.76 36.83,151.76 D22.S2 36.2,151.76 36.2,149.86 v29.84,143.51 | D05.V1 77.47,10.16 73.03,10.16 72.39,10.79 66.04,10.79 65.41,10.16 D01.V1
  Bottom 0.254: v48.9,147.96 48.9,149.86 50.8,151.76 50.8,186.69 38.73,198.75 38.73,205.74 45.72,212.72 D21.V2 | 89.53,8.26 83.19,8.26 82.55,8.89 78.11,8.89 D05.V1 | 89.53,8.26 90.17,8.89 D27.V1 | 89.53,8.26 97.79,8.26 98.42,8.89 102.87,8.89 D28.V1 | D01.V1 64.77,10.16 64.77,12.06 38.1,38.73 38.1,95.89 36.83,97.16 36.83,100.97 C22.M2 36.2,102.23 36.2,104.14 31.11,109.22 13.97,109.22 6.35,116.84 6.35,124.46 10.16,128.27 14.61,128.27 v29.84,143.51
GND
  Top 0.254: 55.24,215.9 52.7,213.36 D21.V1 52.07,212.09 47.62,212.09 29.84,194.31 | 55.24,215.9 52.7,218.44 D21.T1 52.07,219.71 47.62,219.71 46.99,220.34 34.29,220.34 | 55.24,215.9 D21.U1 | D02.U2 24.13,216.53 26.67,219.07 D02.T1 26.67,219.71 26.67,220.34 | 26.67,220.34 26.67,224.79 D02.R1 26.67,226.06 26.67,231.14 | D02.K1 29.84,240.66 29.84,236.85 27.3,234.31 27.3,232.41 D02.N1 26.67,231.14 | 34.29,220.34 34.92,219.71 39.37,219.71 D20.T1 | 26.67,220.34 34.29,220.34 | 12.7,259.71 17.14,259.71 A02.C1 | 12.7,259.71 11.43,259.71 A02.C2 | A02.C1 17.78,259.71 23.5,259.71 D02.C2 24.13,259.71 29.84,259.71 D02.C1 | A02.A1 17.14,266.06 17.14,260.99 A02.C1 | D02.C1 29.84,260.99 29.84,266.06 D02.A1 | D02.C1 30.48,259.71 36.2,259.71 D20.C2 36.83,259.71 37.47,259.08 43.81,259.08 44.45,259.71 48.9,259.71 D21.C2 | D02.R2 20.32,226.06 20.32,231.14 D02.N2 | D02.F1 26.67,250.19 20.95,250.19 D02.F2 20.32,250.19 20.32,245.11 D02.J2 20.32,243.84 17.78,241.3 A02.K1 17.78,240.66 20.32,238.12 D02.L2 20.32,237.49 20.32,232.41 D02.N2 | A02.U2 11.43,216.53 13.97,219.07 A02.T1 13.97,219.71 13.97,224.79 A02.R1 13.97,226.06 13.97,231.14 A02.N1 | A02.R2 7.62,226.06 7.62,231.14 A02.N2 7.62,232.41 7.62,237.49 A02.L2 7.62,238.76 7.62,243.84 A02.J2 7.62,245.11 7.62,250.19 A02.F2 | 12.7,259.71 12.7,252.73 13.97,251.46 A02.F1 | 26.67,231.14 20.95,231.14 D02.N2 | D03.U2 24.13,146.69 26.67,149.22 D03.T1 26.67,149.86 26.67,154.94 D03.R1 26.67,156.21 26.67,161.29 | D03.N2 20.32,161.29 20.32,156.21 D03.R2 20.32,154.94 14.61,154.94 A03.R1 | 17.78,171.45 20.32,168.91 D03.L2 20.32,167.64 20.32,162.56 D03.N2
  Top 0.254: 17.78,171.45 20.32,173.99 D03.J2 20.32,175.26 20.32,180.34 D03.F2 20.95,180.34 25.4,180.34 | 17.78,171.45 A03.K1 | 25.4,180.34 26.67,180.34 D03.F1 | 25.4,180.34 29.84,175.9 29.84,172.09 D03.K1 | 26.67,161.29 20.95,161.29 D03.N2 | 26.67,161.29 D03.N1 | 29.84,194.31 29.84,196.22 D03.A1 | 29.84,194.31 29.84,191.13 D03.C1 | D22.C2 36.2,189.87 30.48,189.87 D03.C1 | A03.A1 17.14,196.22 17.14,191.13 A03.C1 17.78,189.87 23.5,189.87 D03.C2 24.13,189.87 29.84,189.87 D03.C1 | A03.U2 11.43,146.69 13.97,149.22 A03.T1 13.97,149.86 13.97,154.94 A03.R1 | A03.N1 13.97,161.29 13.97,156.21 A03.R1 | A03.R2 7.62,156.21 7.62,161.29 A03.N2 7.62,162.56 7.62,167.64 A03.L2 7.62,168.91 7.62,173.99 A03.J2 7.62,175.26 7.62,180.34 A03.F2 8.26,180.34 13.97,180.34 A03.F1 13.97,181.61 13.97,183.51 11.43,186.06 11.43,189.87 A03.C2 | A04.A1 17.14,132.72 17.14,127.64 A04.C1 17.78,126.36 23.5,126.36 D04.C2 24.13,126.36 29.84,126.36 D04.C1 | D04.C1 30.48,126.36 33.02,123.83 C22.D2 33.66,123.83 36.2,126.36 C22.C2 | 29.84,128.27 29.84,127.64 D04.C1 | 29.84,128.27 29.84,132.72 D04.A1 | 29.84,128.27 43.81,128.27 44.45,127.64 48.9,127.64 C32.C2 | A04.U2 11.43,83.19 13.97,85.72 A04.T1 13.97,86.36 13.97,91.44 A04.R1 13.97,92.71 13.97,97.79 | A04.R2 7.62,92.71 7.62,97.79 A04.N2 | A04.N2 7.62,99.06 7.62,104.14 A04.L2 7.62,105.41 7.62,110.49 A04.J2 7.62,111.76 7.62,116.84 A04.F2 8.26,116.84 13.97,116.84 A04.F1 13.97,118.11 13.97,120.02 11.43,122.56 11.43,126.36 A04.C2 | 13.97,97.79 8.26,97.79 A04.N2 | 13.97,97.79 A04.N1 | 26.04,17.14 19.68,17.14 19.05,16.51 14.61,16.51 C21.T1 | 26.04,17.14 26.67,16.51 C20.T1
  Top 0.254: 34.29,17.14 34.92,16.51 39.37,16.51 C1.T1 | 26.04,17.14 34.29,17.14 | 34.29,17.14 46.99,17.14 47.62,16.51 52.07,16.51 C3.T1 | 22.86,58.42 16.51,58.42 15.88,57.78 11.43,57.78 C21.C2 | 22.86,58.42 23.5,57.78 C20.C2 | 31.11,58.42 31.75,57.78 36.2,57.78 C1.C2 | 31.11,58.42 22.86,58.42 | 31.11,58.42 43.81,58.42 44.45,57.78 48.9,57.78 C3.C2 | D04.U2 24.13,83.19 26.67,85.72 D04.T1 27.3,86.36 29.84,86.36 32.38,88.9 | 26.67,94.61 26.67,97.79 D04.N1 | 26.67,94.61 26.67,92.71 D04.R1 | 26.67,94.61 32.38,88.9 | 32.38,88.9 34.92,86.36 39.37,86.36 C22.T1 | D04.R2 20.32,92.71 20.32,97.79 D04.N2 20.32,99.06 20.32,104.14 D04.L2 20.32,105.41 17.78,107.95 | 17.78,107.95 20.32,110.49 D04.J2 20.32,111.76 20.32,116.84 D04.F2 20.95,116.84 26.67,116.84 D04.F1 | 17.78,107.95 A04.K1
  Bottom 0.254: A02.F1 13.97,250.19 8.26,250.19 A02.F2 | A02.N1 13.97,231.14 8.26,231.14 A02.N2 | D02.R2 20.32,224.79 14.61,224.79 A02.R1 | A03.C2 11.43,189.87 17.14,189.87 A03.C1 | A03.N1 13.97,161.29 8.26,161.29 A03.N2 | A04.C2 11.43,126.36 17.14,126.36 A04.C1 | D04.K1 29.84,107.31 25.4,107.31 23.5,105.41 20.95,105.41 D04.L2 | D04.R1 26.67,91.44 20.95,91.44 D04.R2 | C1.C2 36.2,57.78 36.2,59.69 24.13,71.75 24.13,81.92 D04.U2 | C21.T1 13.97,16.51 11.43,16.51 6.35,21.59 6.35,54.61 8.26,56.52 10.79,56.52 C21.C2 | A04.N1 14.61,97.79 20.32,97.79 D04.N2 | D03.U2 23.5,145.41 23.5,139.7 17.78,133.99 A04.A1
IRQL
  Top 0.254: 47.62,99.69 47.62,102.87 46.35,104.14 C32.L2 | 47.62,99.69 47.62,97.79 39.37,89.53 36.83,89.53 C22.S2 | 80.01,93.98 73.66,93.98 73.03,94.61 68.58,94.61 C2.P1 67.94,94.61 66.67,93.34 61.59,93.34 55.24,99.69 47.62,99.69 | 80.01,93.98 80.64,94.61 C4.P1 | 88.27,93.98 88.9,94.61 93.34,94.61 C27.P1 | 80.01,93.98 88.27,93.98 | 88.27,93.98 100.97,93.98 101.6,94.61 106.05,94.61 C28.P1
MD09L  (via drill 0.61)
  Top 0.254: v41.27,34.29 44.45,34.29 45.09,33.66 64.14,33.66 | 64.14,33.66 64.77,34.29 D01.L1 | 72.39,33.66 73.03,34.29 77.47,34.29 D05.L1 | 64.14,33.66 72.39,33.66 | 85.09,33.66 85.72,34.29 90.17,34.29 D27.L1 | 72.39,33.66 85.09,33.66 | 85.09,33.66 97.79,33.66 98.42,34.29 102.87,34.29 D28.L1
  Bottom 0.254: v41.27,34.29 20.95,13.97 20.95,10.16 C20.V2
MD10L
  Top 0.254: 67.31,33.02 33.02,33.02 31.75,34.29 27.3,34.29 C20.L1 | 67.31,33.02 67.94,32.38 D01.M1 | 75.56,33.02 76.2,32.38 80.64,32.38 D05.M1 | 67.31,33.02 75.56,33.02 | 88.27,33.02 88.9,32.38 93.34,32.38 D27.M1 | 75.56,33.02 88.27,33.02 | 88.27,33.02 100.97,33.02 101.6,32.38 106.05,32.38 D28.M1
MD11L
  Top 0.254: 67.31,24.13 39.37,24.13 34.92,19.68 30.48,19.68 C20.S1 | 67.31,24.13 67.94,24.77 D01.P1 | 75.56,24.13 76.2,24.77 80.64,24.77 D05.P1 | 67.31,24.13 75.56,24.13 | 88.27,24.13 88.9,24.77 93.34,24.77 D27.P1 | 75.56,24.13 88.27,24.13 | 88.27,24.13 100.97,24.13 101.6,24.77 106.05,24.77 D28.P1
N$1
  Top 0.254: D20.B1 40.01,264.16 44.45,264.16 45.72,265.43 54.61,265.43 55.24,266.06 D21.A1
N$2
  Top 0.254: D20.E1 43.18,254.63 45.72,254.63 52.07,260.99 52.07,262.89 D21.B1
N$3
  Bottom 0.254: D20.H1 43.18,248.28 47.62,248.28 49.53,250.19 52.07,250.19 D21.F1
N$4  (via drill 0.61)
  Top 0.254: v50.8,245.11 47.62,241.94 43.18,241.94 D20.K1
  Bottom 0.254: v50.8,245.11 52.7,247.01 55.24,247.01 D21.H1
N$5
  Top 0.254: D20.P1 43.18,229.24 47.62,229.24 49.53,231.14 52.07,231.14 D21.N1
N$6
  Bottom 0.254: D20.M1 43.18,235.59 47.62,235.59 48.26,236.22 54.61,236.22 55.24,235.59 D21.M1
N$7  (via drill 0.61)
  Top 0.254: C20.M2 23.5,32.38 23.5,37.47 C20.K2 | v19.05,48.26 19.05,51.44 17.78,52.7 17.78,56.52 C21.C1
  Bottom 0.254: v19.05,48.26 19.05,40.64 20.95,38.73 23.5,38.73 C20.K2
N$8
  Top 0.254: D20.N2 33.66,231.14 33.66,229.24 41.91,220.98 48.26,220.98 48.9,221.62 D21.S2
N$9  (via drill 0.61)
  Top 0.254: v28.57,60.96 27.94,61.59 17.14,61.59 v16.51,60.96 | v5.71,71.75 5.71,90.17 5.08,90.81 5.08,131.44 v13.97,140.34 | v19.68,146.05 15.24,150.5 v15.24,152.4 | v32.38,229.87 33.02,229.24 33.02,227.97 36.2,224.79 36.2,222.88 D20.S2
  Bottom 0.254: v28.57,60.96 28.57,56.52 33.02,52.07 33.02,48.26 C1.F2 | v5.71,71.75 v16.51,60.96 | v19.68,146.05 v13.97,140.34 | v15.24,152.4 4.45,163.19 4.45,182.88 2.54,184.78 2.54,222.25 10.79,230.5 31.75,230.5 v32.38,229.87
N$10
  Top 0.254: D20.J2 33.66,243.84 36.83,243.84 41.27,239.4 45.09,239.4 45.72,238.76 D21.L2
N$11  (via drill 0.61)
  Top 0.254: v47.62,233.04 v42.55,238.12
  Bottom 0.254: v47.62,233.04 47.62,224.79 43.18,220.34 43.18,216.53 D20.U1 | v42.55,238.12 42.55,239.4 41.27,240.66 41.27,248.28 46.35,253.37 48.9,253.37 D21.E2
N$12  (via drill 0.61)
  Top 0.254: v53.98,231.14 45.72,222.88 43.18,222.88 D20.S1 | v53.98,234.95 v53.98,254
  Bottom 0.254: v53.98,231.14 v53.98,234.95 | v53.98,254 53.98,257.81 53.34,258.44 46.99,258.44 46.35,257.81 D21.D2
N$13
  Top 0.254: D20.F2 33.66,250.19 36.2,250.19 41.27,245.11 41.27,240.66 41.91,240.03 48.26,240.03 48.9,240.66 D21.K2
N$14  (via drill 0.61)
  Top 0.254: v42.55,231.14 36.2,237.49 33.66,237.49 D20.L2
  Bottom 0.254: v42.55,231.14 45.72,227.97 45.72,226.06 D21.R2
N$15  (via drill 0.61)
  Top 0.254: v5.08,29.21 8.26,26.04 10.79,26.04 C21.P2 | v57.15,268.61 17.14,268.61 9.53,260.99 9.53,253.37 v19.05,243.84 | v31.11,231.78 31.11,229.87 32.38,228.6 32.38,226.69 33.02,226.06 D20.R2
  Bottom 0.254: v5.08,29.21 5.08,16.51 14.61,6.99 71.12,6.99 107.95,43.81 107.95,115.57 98.42,125.09 98.42,127.64 108.58,137.79 108.58,217.17 v57.15,268.61 | v19.05,243.84 20.32,242.57 26.67,242.57 32.38,236.85 33.02,236.85 34.29,235.59 34.29,234.95 v31.11,231.78
N$16  (via drill 0.61)
  Top 0.254: 34.92,43.18 36.2,44.45 C1.H2 | 34.92,43.18 33.66,41.91 C1.J2 | v47.62,112.39 48.9,111.12 50.16,111.12 52.07,109.22 56.52,109.22 63.5,102.23 v63.5,94.61 | v44.45,43.81 43.81,43.18 34.92,43.18
  Bottom 0.254: v47.62,112.39 44.45,115.57 44.45,118.11 45.72,119.38 45.72,123.19 C32.D2 | v63.5,94.61 63.5,86.36 54.61,77.47 54.61,64.77 44.45,54.61 v44.45,43.81
N$17  (via drill 0.61)
  Top 0.254: v82.55,88.9 v82.55,73.03 | v50.8,269.88 17.14,269.88 6.35,259.08 6.35,254.63 15.88,245.11 15.88,221.62 22.86,214.63 26.67,214.63 30.48,218.44 33.02,218.44 D20.T2
  Bottom 0.254: v82.55,73.03 82.55,23.5 66.67,7.62 19.05,7.62 14.61,12.06 11.43,12.06 C21.U2 | v82.55,88.9 82.55,116.84 76.2,123.19 76.2,131.44 82.55,137.79 82.55,237.49 50.8,269.24 v50.8,269.88
N$19
  Top 0.254: C21.F1 13.97,48.26 11.43,50.8 C21.E2
N$20
  Bottom 0.254: C21.K1 17.14,38.73 14.61,38.73 9.53,43.81 9.53,52.07 8.26,53.34 C21.D2
N$23  (via drill 0.61)
  Top 0.254: v6.35,57.15 6.35,53.34 7.62,52.07 7.62,48.26 C21.F2 | v6.35,60.96 11.43,66.04 17.78,66.04 33.66,81.92 36.2,81.92 C22.U2
  Bottom 0.254: v6.35,57.15 v6.35,60.96
N$27
  Top 0.254: C20.E1 30.48,50.16 34.92,50.16 39.37,45.72 48.26,45.72 48.9,45.09 C3.H2
N$31
  Bottom 0.254: C3.T2 46.35,15.24 50.8,15.24 57.78,8.26 66.04,8.26 66.67,8.89 66.67,17.14 53.98,29.84 53.98,48.9 55.24,50.16 C3.E1
N$32  (via drill 0.61)
  Top 0.254: v29.21,28.57 v32.38,31.75 | v34.92,44.45 33.02,46.35 32.38,46.35 28.57,50.16 28.57,55.24 29.84,56.52 C20.C1
  Bottom 0.254: v29.21,28.57 20.32,19.68 17.78,19.68 C21.S1 | v32.38,31.75 34.92,34.29 v34.92,44.45
N$33  (via drill 0.61)
  Top 0.254: v31.75,33.02 29.21,33.02 21.59,25.4 20.95,25.4 18.41,27.94 14.61,27.94 C21.N1
  Bottom 0.254: v31.75,33.02 31.75,43.81 34.92,46.99 34.92,56.52 30.48,60.96 30.48,62.87 C20.A1
N$34  (via drill 0.61)
  Top 0.254: v5.08,31.75 7.62,29.21 C21.N2 | v9.53,59.05 26.04,59.05 26.67,59.69 C20.B1
  Bottom 0.254: v5.08,31.75 5.08,54.61 v9.53,59.05
N$35
  Top 0.254: C1.D2 33.66,53.34 36.2,50.8 C1.E2
N$36  (via drill 0.61)
  Top 0.254: v13.97,43.18 11.43,40.64 11.43,38.73 C21.K2
  Bottom 0.254: v13.97,43.18 15.24,43.18 27.94,30.48 35.56,30.48 36.2,31.11 C1.M2
N$37
  Bottom 0.254: C1.V2 33.02,10.16 33.02,13.97 31.75,15.24 31.75,20.32 33.02,21.59 C1.R2
N$38
  Top 0.254: C3.J2 46.35,41.91 50.8,41.91 52.7,43.81 55.24,43.81 C3.H1
N$40  (via drill 0.61)
  Top 0.254: 35.56,26.67 33.66,28.57 C1.N2 | 35.56,26.67 36.2,26.04 C1.P2 | v45.72,115.57 44.45,116.84 44.45,118.11 46.35,120.02 48.9,120.02 C32.E2 | v48.9,112.39 55.24,112.39 70.48,97.16 v74.93,97.16 | v55.88,29.84 38.73,29.84 35.56,26.67
  Bottom 0.254: C21.J2 8.26,40.64 11.43,40.64 22.23,29.84 32.38,29.84 33.02,29.21 C1.N2 | v48.9,112.39 v45.72,115.57 | v74.93,97.16 76.2,95.89 76.2,92.71 59.69,76.2 59.69,61.59 60.33,60.96 60.33,34.29 v55.88,29.84
N$43  (via drill 0.61)
  Top 0.254: 11.43,31.11 11.43,29.21 13.97,26.67 13.97,22.86 C21.R1 | 11.43,31.11 17.14,31.11 C21.M1 | 11.43,31.11 C21.M2 | v28.57,38.1 26.67,36.2 26.04,36.2 25.4,35.56 25.4,31.11 v20.95,26.67 | v52.7,107.95 52.07,107.95 49.53,110.49 46.35,110.49 C32.J2 | v28.57,66.04 v50.8,88.27
  Bottom 0.254: v28.57,38.1 28.57,48.26 27.3,49.53 27.3,53.34 C20.D1 26.67,54.61 25.4,55.88 25.4,60.96 28.57,64.14 v28.57,66.04 | v20.95,26.67 20.32,26.67 17.78,29.21 17.78,31.11 C21.M1 | v52.7,107.95 50.8,106.05 v50.8,88.27
OTP3
  Top 0.254: C1.K2 36.83,38.73 41.27,38.73 45.72,43.18 50.16,43.18 52.07,45.09 52.07,46.99 C3.F1 | 73.66,113.03 67.31,113.03 66.67,113.67 62.23,113.67 C2.H2 | 73.66,113.03 74.3,113.67 C4.H2 | 81.92,113.03 82.55,113.67 87,113.67 C27.H2 | 73.66,113.03 81.92,113.03 | 81.92,113.03 94.61,113.03 95.25,113.67 99.69,113.67 C28.H2
  Bottom 0.254: C3.F1 52.7,48.26 52.7,52.07 57.15,56.52 57.15,75.56 73.03,91.44 73.03,112.39 74.3,113.67 C4.H2
PAUSE
  Top 0.254: C21.T2 8.26,16.51 10.79,19.05 C21.S2
PAUSEL  (via drill 0.61)
  Top 0.254: 76.83,122.56 70.48,122.56 69.85,123.19 65.41,123.19 C2.D1 | 76.83,122.56 77.47,123.19 C4.D1 | 85.09,122.56 85.72,123.19 90.17,123.19 C27.D1 | 85.09,122.56 76.83,122.56 | 85.09,122.56 97.79,122.56 98.42,123.19 102.87,123.19 C28.D1 | C21.H1 17.14,44.45 14.61,41.91 C21.J1 13.97,40.64 v13.97,36.83 | C21.V2 7.62,10.16 7.62,13.97 6.35,15.24 6.35,20.32 7.62,21.59 C21.R2
  Bottom 0.254: v13.97,36.83 9.53,32.38 9.53,24.13 8.26,22.86 C21.R2 | C28.D1 103.5,123.19 106.05,123.19 108.58,120.65 108.58,43.18 71.75,6.35 10.79,6.35 8.26,8.89 C21.V2
POWEROK  (via drill 0.61)
  Top 0.254: v81.28,137.79 81.28,139.7 | 83.19,141.6 83.82,142.24 B27.V2 | 81.28,139.7 83.19,141.6 | 83.19,141.6 91.44,141.6 92.08,142.24 96.52,142.24 B28.V2 | 81.28,139.7 78.74,139.7 76.2,142.24 71.75,142.24 B2.V2
  Bottom 0.254: B1.V2 59.05,143.51 59.05,145.41 67.31,153.67 69.22,153.67 69.85,153.03 69.85,144.78 71.12,143.51 B2.V2 | v81.28,137.79 49.53,106.05 49.53,102.23 C32.M2
SETPAUSE  (via drill 0.61)
  Top 0.254: v33.66,223.52 32.38,222.25 28.57,226.06 v28.57,233.04 | v26.67,234.95 26.67,236.22 25.4,237.49 25.4,245.75 v32.38,252.73 | v87.63,118.11 90.17,115.57 100.97,115.57 107.95,108.58 107.95,88.27 62.23,42.55 53.34,42.55 52.7,41.91 C3.J1
  Bottom 0.254: v33.66,223.52 36.2,226.06 36.2,227.97 D20.P2 | v28.57,233.04 v26.67,234.95 | v32.38,252.73 50.8,271.14 53.34,271.14 85.72,238.76 85.72,120.02 v87.63,118.11
SKIPL  (via drill 0.61)
  Top 0.254: v41.27,104.78 41.27,104.14 36.83,99.69 36.83,95.89 C22.P2 | v42.55,106.05 47.62,106.05 48.9,107.31 C32.K2 49.53,107.31 52.07,107.31 v62.23,97.16 | C2.S1 68.58,88.27 73.03,88.27 73.66,87.63 80.01,87.63 80.64,88.27 C4.S1 81.28,89.53 81.92,89.53 82.55,90.17 92.71,90.17 93.34,89.53 C27.S1 93.98,88.27 98.42,88.27 99.06,87.63 105.41,87.63 106.05,88.27 C28.S1
  Bottom 0.254: v41.27,104.78 v42.55,106.05 | v62.23,97.16 67.94,91.44 67.94,89.53 C2.S1
T2
  Bottom 0.254: A04.T2 8.26,86.36 12.7,86.36 13.34,87 19.68,87 20.32,86.36 D04.T2
TP4  (via drill 0.61)
  Top 0.254: C2.J2 59.05,110.49 63.5,110.49 64.14,109.86 70.48,109.86 71.12,110.49 C4.J2 71.75,110.49 76.2,110.49 76.83,109.86 85.09,109.86 | v66.67,21.59 59.69,14.61 38.73,14.61 38.1,15.24 33.66,15.24 C1.T2 | 85.09,109.86 91.44,109.86 92.08,110.49 96.52,110.49 C28.J2 | 85.09,109.86 84.45,110.49 C27.J2
  Bottom 0.254: v66.67,21.59 66.67,26.67 73.03,33.02 73.03,72.39 85.72,85.09 85.72,109.22 84.45,110.49 C27.J2
V2
  Top 0.254: A04.V2 8.26,78.74 12.7,78.74 13.34,78.11 19.68,78.11 20.32,78.74 D04.V2
VCC  (via drill 0.61)
  Top 0.254: 22.86,64.77 16.51,64.77 15.88,64.14 11.43,64.14 C21.A2 | 22.86,64.77 23.5,64.14 C20.A2 | 31.11,64.77 31.75,64.14 36.2,64.14 C1.A2 | 31.11,64.77 22.86,64.77 | 31.11,64.77 43.81,64.77 44.45,64.14 48.9,64.14 C3.A2 49.53,64.14 57.15,71.75 v57.15,96.52 | D20.A2 36.83,267.33 41.27,267.33 41.91,267.97 48.26,267.97 48.9,267.33 D21.A2 | C22.A2 36.83,132.72 41.27,132.72 41.91,132.08 48.26,132.08 48.9,132.72 C32.A2 | 48.9,180.34 v53.98,175.26 | 48.9,180.34 36.83,192.41 36.83,196.22 D22.A2 | v73.03,204.47 48.9,180.34 | v57.15,122.56 v62.23,117.47
  Bottom 0.254: v53.98,175.26 53.98,138.43 49.53,133.99 C32.A2 49.53,132.72 49.53,130.18 v57.15,122.56 | v73.03,204.47 73.03,240.03 49.53,263.52 49.53,266.06 D21.A2 | v57.15,96.52 57.15,112.39 v62.23,117.47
